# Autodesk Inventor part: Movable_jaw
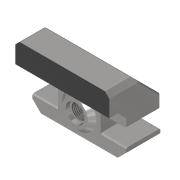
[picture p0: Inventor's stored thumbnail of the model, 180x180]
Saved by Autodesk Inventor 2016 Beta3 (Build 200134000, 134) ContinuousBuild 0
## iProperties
Created: 2016-02
Part Number: Movable_jaw
Material: Steel, Carbon
Document SubType Name: Modeling
Designer: Vertex
Mass: 2400.66 g
Surface Area: 389.201 cm^2
Volume: 305.817 cm^3
Density: 7.85 g/cm^3
Appearance: Semi-Polished
Title: Apoio
Author: Vertex
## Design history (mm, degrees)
sketch "Sketch1"
  geometry: L1 (85.224, 80)-(35.224, 80); L2 (30.224, 15)-(30.224, 0); L3 (30.224, 15)-(60.224, 15); L4 (60.224, 35)-(60.224, 15); L5 (30.224, 35)-(60.224, 35); L6 (30.224, 75)-(30.224, 35); L7 (30.224, 75)-(35.224, 80); L8 (85.224, 80)-(135.224, 80); L9 (140.224, 15)-(140.224, 0); L10 (140.224, 15)-(110.224, 15); L11 (110.224, 35)-(110.224, 15); L12 (140.224, 35)-(110.224, 35); L13 (140.224, 75)-(140.224, 35); L14 (140.224, 75)-(135.224, 80); L15 (30.224, 0)-(140.224, 0); L16 (85.224, 90.232)-(85.224, -5); 5 further points
  constraints: 32 end point, 5 point on line, 2 parallel, 1 horizontal, 1 vertical
  dimensions: "d5" = 5 distance of L6.start point (30.224, 80); "d6" = 5 distance of L1.end point (30.224, 80) (= d5); "d9" = 20 distance between parallel lines of L12 L10; "d10" = 45 distance from line of L8 L12.start; "d67" = 15 distance of L9.end L9.start; "d68" = 45 vertical distance of L5.start L1.end; "d89" = 30 distance of L4.start L5.start; "d90" = 30 distance between parallel lines of L13 L11; "d94" = 110 distance of L9.end L2.end; "d95" = 30 distance of L2.start L3.end; "d96" = 110 distance between parallel lines of L13 L6
extrude "Extrusion1" new body sketch "Sketch1" stored distance "d11" = 40; taper "d12" = 0 deg
hole "Hole1" diameter "d15" = 17.83; stored, may be unused: countersink angle "d19" = 90 deg, drill point angle "d21" = 118 deg; dims "d13" = 25, "d14" = 25, "d16" = 40, "d17" = 3.75, "d18" = 2.5, "d20" = 49.3
workplane "Work Plane1"
sketch "Sketch2"
  geometry: C1 r 8.915 at (85.224, 25) reference; C2 r 11 at (85.224, 25); C3 r 20 at (85.224, 25); 1 further point
  constraints: 2 centre point, 2 coincident
  dimensions: "d92" = 22 diameter of C2; "d93" = 40 diameter of C3
extrude "Extrusion2" join sketch "Sketch2" distance "d35" = 5; taper "d36" = 0 deg
chamfer "Chamfer4" distance "d69" = 30; stored, may be unused: second distance "d70" = 1.25, angle "d71" = 45 deg
fillet "Fillet10" dims "d72" = 2
sketch "Sketch3"
  geometry: L1 (32.224, 35)-(60.224, 35) reference; L2 (60.224, 35)-(60.224, 13) reference; L3 (30.224, 13)-(60.224, 13) reference; L4 (30.224, 0)-(140.224, 0) reference; L5 (110.224, 13)-(140.224, 13) reference; L6 (110.224, 35)-(110.224, 13) reference; L7 (110.224, 35)-(138.224, 35) reference; L8 (140.224, 37)-(140.224, 74.172) reference; L9 (139.638, 75.586)-(135.809, 79.414) reference; L10 (134.395, 80)-(36.052, 80) reference; L11 (34.638, 79.414)-(30.809, 75.586) reference; L12 (30.224, 74.172)-(30.224, 37) reference; L13 (30.224, 74.172)-(30.224, 37) reference; L14 (30.224, 55)-(140.224, 55); L15 (140.224, 37)-(140.224, 74.172) reference; L16 (140.224, 0)-(140.224, 13) reference; L17 (30.224, 13)-(30.224, 0) reference; C1 r 8.915 at (85.224, 25) reference; C2 r 11 at (85.224, 25) reference; C3 r 20 at (85.224, 25) reference; A1 r 2 centre (32.224, 37) between (30.224, 37) and (32.224, 35) reference; A2 r 2 centre (138.224, 37) between (138.224, 35) and (140.224, 37) reference; A3 r 2 centre (138.224, 74.172) between (140.224, 74.172) and (139.638, 75.586) reference; A4 r 2 centre (134.395, 78) between (135.809, 79.414) and (134.395, 80) reference; A5 r 2 centre (36.052, 78) between (36.052, 80) and (34.638, 79.414) reference; A6 r 2 centre (32.224, 74.172) between (30.809, 75.586) and (30.224, 74.172) reference; 1 further point
  constraints: 2 end point, 2 point on line, 1 perpendicular
extrude "Extrusion3" join sketch "Sketch3" distance "d73" = 20; taper "d74" = 0 deg
chamfer "Chamfer5" distance "d75" = 10; stored, may be unused: second distance "d76" = 1.25, angle "d77" = 45 deg
mirror "Mirror8"
chamfer "Chamfer6" distance "d97" = 5; stored, may be unused: second distance "d98" = 1.25, angle "d99" = 45 deg
body "Solid1"
node "Projected Loop1"
